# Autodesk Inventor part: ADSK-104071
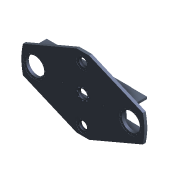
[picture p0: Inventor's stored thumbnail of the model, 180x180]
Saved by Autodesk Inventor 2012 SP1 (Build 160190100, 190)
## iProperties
Shininess: 0.0
Created: 2000-10
Part Number: ADSK-104071
Document SubType Name: Modeling
Designer: gao
Stock Number: ADSK-104071
Density: 1 g/cm^3
Material: Default
Density: 0.0
Volumn: 0.0
Area: 0.0
PropertySet Name: Model Information
Control State: 0
Master: False
Checked Out: False
Author: gao
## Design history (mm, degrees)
node "Extrusion1" dims "d1" = 31.75, "d2" = 0
  sketch "Sketch1"
    geometry: C1 r 685.8 at (0, 0)
    constraints: 1 centre point
    dimensions: "d0" = 1371.6 diameter of C1
node "Hole1" dims "d3" = 101.6, "d4" = 9.525, "d5" = 6.35, "d6" = 60 deg, "d7" = 19.05, "d8" = 118 deg
  sketch "Sketch2"
    geometry: C1 r 685.8 at (0, 0) reference; 1 further point
    constraints: 1 coincident
node "Hole2" dims "d11" = 203.2, "d12" = 9.525, "d13" = 6.35, "d14" = 60 deg, "d15" = 19.05, "d16" = 118 deg
  sketch "Sketch3"
    geometry: C1 r 50.8 at (0, 0) reference; 2 further points
    dimensions: "d9" = 533.4 distance of C1.centre point (-533.4, 0); "d10" = 533.4 distance of point (533.4, 0) C1.centre (= d9)
node "Extrusion2" dims "d21" = 127, "d22" = 0
  sketch "Sketch4"
    geometry: L1 (-558.8, 177.8)-(558.8, 177.8); L2 (558.8, 177.8)-(558.8, 152.4); L3 (558.8, 152.4)-(-558.8, 152.4); L4 (-558.8, 152.4)-(-558.8, 177.8); C1 r 50.8 at (0, 0) reference
    constraints: 8 end point, 2 parallel, 1 horizontal, 1 perpendicular
    dimensions: "d17" = 25.4 distance of L1.end L2.end; "d18" = 1117.6 distance of L1.start L1.end; "d19" = 558.8 horizontal distance of L1.start C1.centre; "d20" = 152.4 distance from line of L3 C1.centre
workaxis "Work Axis1"
workplane "Work Plane1"
node "Mirror1"
node "Hole3" dims "d31" = 10.3124, "d32" = 14.224, "d33" = 9.525, "d34" = 60 deg, "d35" = 19.05, "d36" = 118 deg
  sketch "Sketch6" dims "d30" = 123.825
    geometry: A1 r 685.8 centre (0, 0) between (-637.029, 254) and (-637.029, -254) reference; 2 further points
    constraints: 1 coincident, 1 vertical alignment, 2 other
node "Circular Pattern1" dims "d37" = 80, "d39" = 45 deg
node "Extrusion4" dims "d55" = 1.524, "d56" = 0
  sketch "Sketch8"
    geometry: C1 r 5.156 at (-61.913, 0) reference; C2 r 5.156 at (-43.779, -43.779) reference; C3 r 5.156 at (0, -61.913) reference; C4 r 5.156 at (43.779, -43.779) reference; C5 r 5.156 at (61.913, 0) reference; C6 r 5.156 at (43.779, 43.779) reference; C7 r 5.156 at (-43.779, 43.779) reference; C8 r 5.156 at (0, 61.913) reference; C9 r 50.8 at (0, 0) reference; C10 r 79.375 at (0, 0)
    constraints: 1 centre point, 1 coincident
    dimensions: "d54" = 158.75 diameter of C10
node "Extrusion5" dims "d60" = 3.175, "d61" = 0
  sketch "Sketch9"
    geometry: L1 (-558.8, 177.8)-(558.8, 177.8) reference; L2 (558.8, 152.4)-(-558.8, 152.4) reference; L3 (558.8, 177.8)-(558.8, 152.4) reference; L4 (381, 177.8)-(381, 152.4)
    constraints: 2 end point, 2 point on line, 1 perpendicular
    dimensions: "d59" = 177.8 distance between parallel lines of L4 L3
node "Mirror3"
workplane "Work Plane2"
node "Mirror4"
node "Hole5" dims "d63" = 10.5918, "d64" = 14.224, "d65" = 9.525, "d66" = 60 deg, "d67" = 38.1, "d68" = 118 deg, "d154" = 25.4
  sketch "Sketch10"
    geometry: C1 r 6.731 at (460.375, 165.1) reference; C2 r 6.731 at (523.875, 165.1) reference; 2 further points
    constraints: 2 coincident
node "Mirror5"
node "Mirror6"
node "Extrusion6" dims "d71" = 127, "d72" = 0
  sketch "Sketch11"
    geometry: L1 (558.8, 152.4)-(-558.8, 152.4) reference; L2 (-558.8, -152.4)-(558.8, -152.4) reference; L3 (558.8, -152.4)-(558.8, -177.8) reference; L4 (-330.2, 152.4)-(-330.2, -152.4); L5 (-304.8, 152.4)-(-304.8, -152.4); A1 r 685.8 centre (0, 0) between (-661.275, 181.76) and (-661.275, -181.76) reference
    constraints: 4 end point, 4 point on line, 1 parallel, 1 perpendicular
    dimensions: "d69" = 25.4 distance between parallel lines of L4 L5; "d70" = 304.8 distance from line of L5 A1.centre
node "Mirror7"
node "Hole6" dims "d75" = 6.4008, "d76" = 9.525, "d77" = 6.35, "d78" = 60 deg, "d79" = 19.05, "d80" = 118 deg, "d155" = 12.7
  sketch "Sketch12"
    geometry: C1 r 50.8 at (0, 0) reference; 2 further points
    dimensions: "d73" = 228.6 distance of point (228.6, 0) C1.centre; "d74" = 228.6 distance of C1.centre point (-228.6, 0) (= d73)
node "Extrusion7" dims "d83" = 1.524, "d84" = 0
  sketch "Sketch13"
    geometry: C1 r 3.899 at (-614.222, 80.822) reference; C2 r 3.899 at (-562.983, 110.405) reference; C3 r 3.899 at (-503.817, 110.405) reference; C4 r 3.899 at (-452.578, 80.822) reference; C5 r 3.899 at (-422.995, 29.583) reference; C6 r 3.899 at (-422.995, -29.583) reference; C7 r 3.899 at (-452.578, -80.822) reference; C8 r 3.899 at (-503.817, -110.405) reference; C9 r 3.899 at (-562.983, -110.405) reference; C10 r 3.899 at (-614.222, -80.822) reference; C11 r 3.899 at (-643.805, 29.583) reference; C12 r 3.899 at (-643.805, -29.583) reference; C13 r 101.6 at (-533.4, 0) reference; C14 r 101.6 at (533.4, 0) reference; C15 r 130.175 at (533.4, 0); C16 r 130.175 at (-533.4, 0)
    constraints: 2 centre point, 2 coincident
    dimensions: "d81" = 260.35 diameter of C16; "d82" = 260.35 diameter of C15 (= d81)
node "Hole7" dims "d90" = 90, "d91" = 9.525, "d92" = 6.35, "d93" = 60 deg, "d94" = 19.05, "d95" = 118 deg
  sketch "Sketch15"
    geometry: C1 r 50.8 at (0, 0) reference; 2 further points
    dimensions: "d88" = 304.8 distance of point (0, 304.8) C1.centre; "d89" = 304.8 distance of point (0, -304.8) C1.centre (= d88)
node "Extrusion9" dims "d99" = 25.4, "d100" = 0
  sketch "Sketch16"
    geometry: L1 (-552.414, 406.4)-(552.414, 406.4); L2 (-552.414, -406.4)-(552.414, -406.4); C1 r 50.8 at (0, 0) reference; A1 r 685.8 centre (0, 0) between (-552.414, 406.4) and (552.414, 406.4) reference
    constraints: 4 end point, 4 point on circle, 1 horizontal, 1 parallel
    dimensions: "d96" = 406.4 distance from line of L1 C1.centre; "d98" = 406.4 distance from line of C1.centre L2 (= d96)
node "Extrusion10" dims "d103" = 25.4, "d104" = 0
  sketch "Sketch17"
    geometry: L1 (552.414, 406.4)-(-552.414, 406.4) reference; L2 (-668.652, 152.4)-(-70.266, 406.4); A1 r 685.8 centre (0, 0) between (-552.414, 406.4) and (-552.414, -406.4) reference
    constraints: 2 end point, 1 point on circle, 1 point on line
    dimensions: "d101" = 152.4 vertical distance of L2.start A1.centre; "d102" = 23 deg angle of L1 L2
node "Circular Pattern4" dims "d105" = 20, "d107" = 180 deg
node "Mirror8"
node "Extrusion11" dims "d110" = 1.524, "d111" = 0
  sketch "Sketch18"
    geometry: C1 r 45 at (0, 304.8) reference; C2 r 45 at (0, -304.8) reference; C3 r 76.2 at (0, 304.8); C4 r 76.2 at (0, -304.8)
    constraints: 2 centre point, 2 coincident
    dimensions: "d108" = 152.4 diameter of C3; "d109" = 152.4 diameter of C4 (= d108)
node "Extrusion12" dims "d114" = 3.175, "d115" = 0
  sketch "Sketch19"
    geometry: L1 (-330.2, -152.4)-(-330.2, 152.4) reference; L2 (330.2, -152.4)-(330.2, 152.4) reference; L3 (304.8, 152.4)-(304.8, -152.4) reference; L4 (-304.8, 152.4)-(-304.8, -152.4) reference; L5 (-330.2, 101.6)-(-304.8, 101.6); L6 (304.8, 101.6)-(330.2, 101.6); L7 (-330.2, -101.6)-(-304.8, -101.6); L8 (304.8, -101.6)-(330.2, -101.6); C1 r 50.8 at (0, 0) reference
    constraints: 8 end point, 8 point on line, 4 perpendicular
node "Hole8" dims "d119" = 10.5918, "d120" = 9.525, "d121" = 6.35, "d122" = 60 deg, "d123" = 38.1, "d124" = 118 deg, "d156" = 25.4
  sketch "Sketch20"
    geometry: L1 (330.2, 101.6)-(330.2, -101.6) reference; C1 r 50.8 at (0, 0) reference; 2 further points
    dimensions: "d116" = 76.2 distance of point (317.5, -38.1) point (317.5, 38.1); "d117" = 38.1 vertical distance of C1.centre point (317.5, 38.1); "d118" = 12.7 distance from line of point (317.5, 38.1) L1
node "Mirror9"
node "Hole9" dims "d128" = 7.7978, "d129" = 9.525, "d130" = 6.35, "d131" = 60 deg, "d132" = 19.05, "d133" = 118 deg, "d157" = 12.7
  sketch "Sketch21" dims "d126" = 228.6
    geometry: L1 (0, 0)-(-15.636, 178.725); L2 (0, 0)-(0, 153.292); C1 r 130.175 at (0, 0) reference; 1 further point
    constraints: 4 end point, 1 coincident, 1 point on line, 1 vertical, 3 other
    dimensions: "d127" = 5 deg angle of L1 L2
node "Circular Pattern5" dims "d134" = 120, "d136" = 30 deg
node "Circular Pattern6" dims "d137" = 20, "d139" = 180 deg
node "Mirror10"
node "Hole10" dims "d142" = 6.4008, "d143" = 9.525, "d144" = 6.35, "d145" = 60 deg, "d146" = 19.05, "d147" = 118 deg, "d158" = 12.7
  sketch "Sketch23"
    geometry: L1 (0, 0)-(48.789, -104.628); L2 (0, 0)-(0, -213.887); C1 r 76.2 at (0, 0) reference; C2 r 57.5 at (0, 0); 1 further point
    constraints: 4 end point, 1 centre point, 1 coincident, 1 midpoint, 1 vertical
    dimensions: "d140" = 115 diameter of C2; "d141" = 25 deg angle of L2 L1
node "Circular Pattern7" dims "d148" = 40, "d150" = 90 deg
node "Circular Pattern8" dims "d151" = 20, "d153" = 180 deg
workaxis "Work Axis2"
workaxis "Work Axis3"
sketch "Sketch24"
  geometry: C1 r 3.572 at (420.827, 111.125) reference; C2 r 3.572 at (477.977, 111.125) reference; 2 further points
  constraints: 2 coincident
hole "Hole11" sketch "Sketch24" at (420.827, 111.125), (477.977, 111.125) diameter "d159" = 6.4008; stored, may be unused: countersink angle "d163" = 60 deg, drill point angle "d165" = 118 deg; dims "d160" = 12.7, "d161" = 9.525, "d162" = 6.35, "d164" = 19.05
sketch "Sketch25"
  geometry: C1 r 3.572 at (699.643, -111.125) reference; C2 r 3.572 at (756.793, -111.125) reference; 2 further points
  constraints: 2 coincident
hole "Hole12" sketch "Sketch25" at (699.643, -111.125), (756.793, -111.125) diameter "d166" = 6.4008; stored, may be unused: countersink angle "d170" = 60 deg, drill point angle "d172" = 118 deg; dims "d167" = 12.7, "d168" = 9.525, "d169" = 6.35, "d171" = 19.05
body "Solid1"
other parameters: "d23" = 0, "d62" = 0, "d112" = 203.2, "d113" = 101.6
